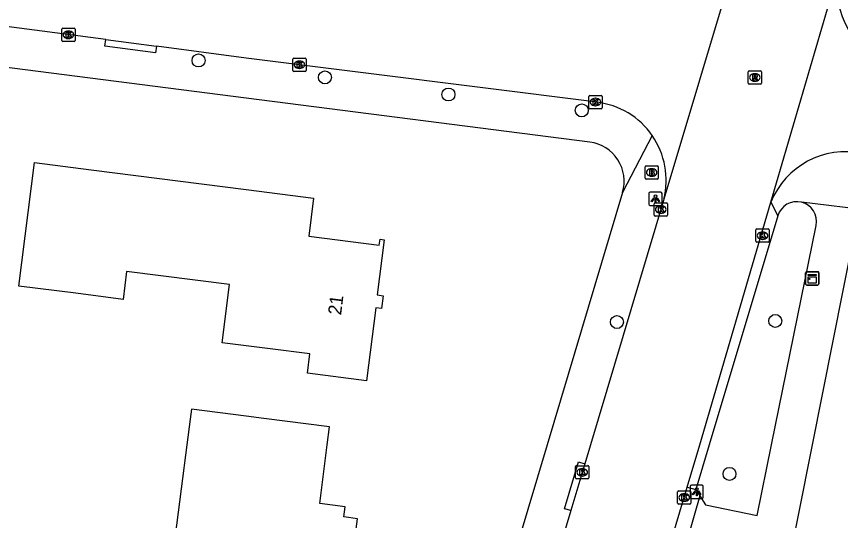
# Model space of a CAD drawing. Extents: x 162186 to 163152, y 385513 to 386513.
# Drawn here: x 162482.7 to 162544.8, y 385994.3 to 386032.3 of the extents above; entities that cross this region are included whole.
import ezdxf

# ---------------------------------------------------------------- set-up
doc = ezdxf.new("R2010")
doc.units = 0
for name, color, linetype in [('IMGEO_Boom', 7, 'Continuous'), ('IMGEO_Brandkraan', 7, 'Continuous'), ('IMGEO_Kast', 7, 'Continuous'), ('IMGEO_Kolk', 7, 'Continuous'), ('IMGEO_Lichtpunt', 7, 'Continuous'), ('IMGEO_Pand', 7, 'Continuous'), ('IMGEO_Pand_nummerreeks', 7, 'Continuous'), ('IMGEO_Rijbaan_lokaal_gesloten', 7, 'Continuous'), ('IMGEO_Rijbaan_lokaal_open', 7, 'Continuous'), ('IMGEO_Rioolput', 7, 'Continuous'), ('IMGEO_Voetpad_open', 7, 'Continuous')]:
    doc.layers.add(name, color=color, linetype=linetype)

msp = doc.modelspace()

# ---------------------------------------------------------------- linework, layer by layer
at = {"layer": 'IMGEO_Boom'}
for centre in [(162496.412, 386028.965), (162505.944, 386027.69), (162515.26, 386026.402), (162525.313, 386025.203), (162527.966, 386009.257), (162539.91, 386009.339), (162536.455, 385997.816)]:
    msp.add_circle(centre, 0.489, dxfattribs=at)
at = {"layer": 'IMGEO_Brandkraan'}
for p, q in [((162530.085, 386020.102), (162530.085, 386020.954)), ((162530.16, 386021.028), (162531.012, 386021.028)), ((162531.086, 386020.954), (162531.086, 386020.102)), ((162530.596, 386020.248), (162530.571, 386020.248)), ((162530.573, 386020.808), (162530.598, 386020.808)), ((162531.012, 386020.028), (162530.16, 386020.028))]:
    msp.add_line(p, q, dxfattribs=at)
for points in [[(162530.085, 386020.102), (162530.085, 386020.954)], [(162530.16, 386021.028), (162531.012, 386021.028)], [(162531.086, 386020.954), (162531.086, 386020.102)], [(162530.433, 386020.728), (162530.433, 386020.328), (162530.646, 386020.328)], [(162530.664, 386020.728), (162530.433, 386020.728)], [(162530.612, 386020.647), (162530.558, 386020.647), (162530.558, 386020.571)], [(162530.558, 386020.571), (162530.611, 386020.571)], [(162530.62, 386020.495), (162530.558, 386020.495), (162530.558, 386020.414)], [(162530.558, 386020.414), (162530.62, 386020.414)], [(162531.012, 386020.028), (162530.16, 386020.028)]]:
    msp.add_lwpolyline(points, dxfattribs=at)
for centre, radius, start, end in [((162530.162, 386020.952), 0.0765, 91.55205, 178.44795), ((162530.162, 386020.952), 0.0765, 91.55205, 178.44795), ((162531.01, 386020.952), 0.0765, 1.55205, 88.44795), ((162531.01, 386020.952), 0.0765, 1.55205, 88.44795), ((162530.613, 386020.609), 0.0379, 267.82845, 90.93552), ((162530.621, 386020.454), 0.0404, 269.87594, 90.50774), ((162530.652, 386020.579), 0.251, 268.66757, 293.53466), ((162530.668, 386020.583), 0.145, 59.4692, 91.53667), ((162530.693, 386020.63), 0.0922, 285.51372, 58.15012), ((162530.698, 386020.438), 0.105, 301.31148, 78.98903), ((162530.162, 386020.104), 0.0765, 181.55205, 268.44795), ((162530.162, 386020.104), 0.0765, 181.55205, 268.44795), ((162531.01, 386020.104), 0.0765, 271.55205, 358.44795), ((162531.01, 386020.104), 0.0765, 271.55205, 358.44795)]:
    msp.add_arc(centre, radius, start, end, dxfattribs=at)
for centre, major_axis, ratio, start_param, end_param in [((162530.572, 386020.528), (-0.387, 0.002), 0.722429, 4.712389, 7.853982), ((162530.597, 386020.528), (-0.39, 0.002), 0.717154, 1.570796, 4.712389)]:
    msp.add_ellipse(centre, major_axis=major_axis, ratio=ratio, start_param=start_param, end_param=end_param, dxfattribs=at)
at = {"layer": 'IMGEO_Kast'}
for p, q in [((162542.199, 386012.123), (162542.199, 386012.964)), ((162542.199, 386012.964), (162542.199, 386012.123)), ((162542.274, 386013.048), (162543.115, 386013.048)), ((162543.115, 386013.048), (162542.274, 386013.048)), ((162543.199, 386012.973), (162543.199, 386012.132)), ((162543.199, 386012.132), (162543.199, 386012.973)), ((162543.124, 386012.048), (162542.283, 386012.048)), ((162542.283, 386012.048), (162543.124, 386012.048))]:
    msp.add_line(p, q, dxfattribs=at)
for points in [[(162542.394, 386012.838), (162542.994, 386012.838), (162542.994, 386012.753), (162542.394, 386012.753), (162542.394, 386012.838)], [(162542.394, 386012.663), (162542.994, 386012.663), (162542.994, 386012.174), (162542.394, 386012.174), (162542.394, 386012.663)]]:
    msp.add_lwpolyline(points, dxfattribs=at)
msp.add_circle((162542.478, 386012.512), 0.0377, dxfattribs=at)
for centre, start, end in [((162542.277, 386012.97), 92.4484, 184.28452), ((162542.277, 386012.97), 92.4484, 184.28452), ((162543.121, 386012.97), 2.4484, 94.28452), ((162543.121, 386012.97), 2.4484, 94.28452), ((162542.277, 386012.126), 182.4484, 274.28452), ((162542.277, 386012.126), 182.4484, 274.28452), ((162543.121, 386012.126), 272.4484, 4.28452), ((162543.121, 386012.126), 272.4484, 4.28452)]:
    msp.add_arc(centre, 0.0779, start, end, dxfattribs=at)
at = {"layer": 'IMGEO_Kolk'}
for p, q in [((162486.175, 386031.402), (162487.027, 386031.402)), ((162486.1, 386030.476), (162486.1, 386031.328)), ((162486.588, 386031.182), (162486.613, 386031.182)), ((162487.101, 386031.328), (162487.101, 386030.476)), ((162487.027, 386030.402), (162486.175, 386030.402)), ((162486.611, 386030.622), (162486.586, 386030.622)), ((162503.52, 386028.218), (162503.52, 386029.07)), ((162503.595, 386029.144), (162504.447, 386029.144)), ((162504.008, 386028.924), (162504.033, 386028.924)), ((162504.521, 386029.07), (162504.521, 386028.218)), ((162504.031, 386028.364), (162504.006, 386028.364)), ((162504.447, 386028.144), (162503.595, 386028.144)), ((162525.842, 386025.408), (162525.842, 386026.26)), ((162525.917, 386026.334), (162526.769, 386026.334)), ((162526.33, 386026.114), (162526.355, 386026.114)), ((162526.843, 386026.26), (162526.843, 386025.408)), ((162526.769, 386025.334), (162525.917, 386025.334)), ((162526.353, 386025.554), (162526.328, 386025.554)), ((162530.773, 386017.314), (162530.773, 386018.166)), ((162530.848, 386018.24), (162531.7, 386018.24)), ((162531.261, 386018.02), (162531.286, 386018.02)), ((162531.774, 386018.166), (162531.774, 386017.314)), ((162531.7, 386017.24), (162530.848, 386017.24)), ((162531.284, 386017.46), (162531.259, 386017.46)), ((162538.447, 386015.342), (162538.447, 386016.194)), ((162538.522, 386016.268), (162539.374, 386016.268)), ((162538.935, 386016.048), (162538.96, 386016.048)), ((162539.448, 386016.194), (162539.448, 386015.342)), ((162539.374, 386015.268), (162538.522, 386015.268)), ((162538.958, 386015.488), (162538.933, 386015.488)), ((162524.848, 385997.51), (162524.848, 385998.362)), ((162524.923, 385998.436), (162525.775, 385998.436)), ((162525.336, 385998.216), (162525.361, 385998.216)), ((162525.849, 385998.362), (162525.849, 385997.51)), ((162525.775, 385997.436), (162524.923, 385997.436)), ((162525.359, 385997.656), (162525.334, 385997.656)), ((162532.546, 385995.609), (162532.546, 385996.461)), ((162532.621, 385996.535), (162533.473, 385996.535)), ((162533.034, 385996.315), (162533.059, 385996.315)), ((162533.547, 385996.461), (162533.547, 385995.609)), ((162533.473, 385995.535), (162532.621, 385995.535)), ((162533.057, 385995.755), (162533.032, 385995.755))]:
    msp.add_line(p, q, dxfattribs=at)
for points in [[(162486.175, 386031.402), (162487.027, 386031.402)], [(162486.1, 386030.476), (162486.1, 386031.328)], [(162486.421, 386031.102), (162486.544, 386031.102), (162486.544, 386030.951), (162486.674, 386031.102), (162486.838, 386031.102), (162486.692, 386030.951), (162486.845, 386030.702), (162486.693, 386030.702), (162486.608, 386030.866), (162486.544, 386030.799), (162486.544, 386030.702), (162486.421, 386030.702), (162486.421, 386031.102)], [(162487.101, 386031.328), (162487.101, 386030.476)], [(162487.027, 386030.402), (162486.175, 386030.402)], [(162503.52, 386028.218), (162503.52, 386029.07)], [(162503.595, 386029.144), (162504.447, 386029.144)], [(162504.521, 386029.07), (162504.521, 386028.218)], [(162503.841, 386028.844), (162503.964, 386028.844), (162503.964, 386028.693), (162504.094, 386028.844), (162504.258, 386028.844), (162504.112, 386028.693), (162504.265, 386028.444), (162504.113, 386028.444), (162504.028, 386028.608), (162503.964, 386028.541), (162503.964, 386028.444), (162503.841, 386028.444), (162503.841, 386028.844)], [(162504.447, 386028.144), (162503.595, 386028.144)], [(162525.842, 386025.408), (162525.842, 386026.26)], [(162525.917, 386026.334), (162526.769, 386026.334)], [(162526.163, 386026.034), (162526.286, 386026.034), (162526.286, 386025.883), (162526.416, 386026.034), (162526.58, 386026.034), (162526.434, 386025.883), (162526.587, 386025.634), (162526.435, 386025.634), (162526.35, 386025.798), (162526.286, 386025.731), (162526.286, 386025.634), (162526.163, 386025.634), (162526.163, 386026.034)], [(162526.843, 386026.26), (162526.843, 386025.408)], [(162526.769, 386025.334), (162525.917, 386025.334)], [(162530.773, 386017.314), (162530.773, 386018.166)], [(162530.848, 386018.24), (162531.7, 386018.24)], [(162531.094, 386017.94), (162531.217, 386017.94), (162531.217, 386017.789), (162531.347, 386017.94), (162531.511, 386017.94), (162531.365, 386017.789), (162531.518, 386017.54), (162531.366, 386017.54), (162531.281, 386017.704), (162531.217, 386017.637), (162531.217, 386017.54), (162531.094, 386017.54), (162531.094, 386017.94)], [(162531.774, 386018.166), (162531.774, 386017.314)], [(162531.7, 386017.24), (162530.848, 386017.24)], [(162538.447, 386015.342), (162538.447, 386016.194)], [(162538.522, 386016.268), (162539.374, 386016.268)], [(162538.768, 386015.968), (162538.891, 386015.968), (162538.891, 386015.817), (162539.021, 386015.968), (162539.185, 386015.968), (162539.039, 386015.817), (162539.192, 386015.568), (162539.04, 386015.568), (162538.955, 386015.732), (162538.891, 386015.665), (162538.891, 386015.568), (162538.768, 386015.568), (162538.768, 386015.968)], [(162539.448, 386016.194), (162539.448, 386015.342)], [(162539.374, 386015.268), (162538.522, 386015.268)], [(162524.848, 385997.51), (162524.848, 385998.362)], [(162524.923, 385998.436), (162525.775, 385998.436)], [(162525.169, 385998.136), (162525.292, 385998.136), (162525.292, 385997.985), (162525.422, 385998.136), (162525.586, 385998.136), (162525.44, 385997.985), (162525.593, 385997.736), (162525.441, 385997.736), (162525.356, 385997.9), (162525.292, 385997.833), (162525.292, 385997.736), (162525.169, 385997.736), (162525.169, 385998.136)], [(162525.849, 385998.362), (162525.849, 385997.51)], [(162525.775, 385997.436), (162524.923, 385997.436)], [(162532.546, 385995.609), (162532.546, 385996.461)], [(162532.621, 385996.535), (162533.473, 385996.535)], [(162532.867, 385996.235), (162532.99, 385996.235), (162532.99, 385996.084), (162533.12, 385996.235), (162533.284, 385996.235), (162533.138, 385996.084), (162533.291, 385995.835), (162533.139, 385995.835), (162533.054, 385995.999), (162532.99, 385995.932), (162532.99, 385995.835), (162532.867, 385995.835), (162532.867, 385996.235)], [(162533.547, 385996.461), (162533.547, 385995.609)], [(162533.473, 385995.535), (162532.621, 385995.535)]]:
    msp.add_lwpolyline(points, dxfattribs=at)
for centre, start, end in [((162486.177, 386031.326), 91.55205, 178.44795), ((162486.177, 386031.326), 91.55205, 178.44795), ((162487.025, 386031.326), 1.55205, 88.44795), ((162487.025, 386031.326), 1.55205, 88.44795), ((162486.177, 386030.478), 181.55205, 268.44795), ((162486.177, 386030.478), 181.55205, 268.44795), ((162487.025, 386030.478), 271.55205, 358.44795), ((162487.025, 386030.478), 271.55205, 358.44795), ((162503.597, 386029.068), 91.55205, 178.44795), ((162503.597, 386029.068), 91.55205, 178.44795), ((162504.445, 386029.068), 1.55205, 88.44795), ((162504.445, 386029.068), 1.55205, 88.44795), ((162503.597, 386028.22), 181.55205, 268.44795), ((162503.597, 386028.22), 181.55205, 268.44795), ((162504.445, 386028.22), 271.55205, 358.44795), ((162504.445, 386028.22), 271.55205, 358.44795), ((162525.919, 386026.258), 91.55205, 178.44795), ((162525.919, 386026.258), 91.55205, 178.44795), ((162526.767, 386026.258), 1.55205, 88.44795), ((162526.767, 386026.258), 1.55205, 88.44795), ((162525.919, 386025.41), 181.55205, 268.44795), ((162525.919, 386025.41), 181.55205, 268.44795), ((162526.767, 386025.41), 271.55205, 358.44795), ((162526.767, 386025.41), 271.55205, 358.44795), ((162530.85, 386018.164), 91.55205, 178.44795), ((162530.85, 386018.164), 91.55205, 178.44795), ((162531.698, 386018.164), 1.55205, 88.44795), ((162531.698, 386018.164), 1.55205, 88.44795), ((162530.85, 386017.316), 181.55205, 268.44795), ((162530.85, 386017.316), 181.55205, 268.44795), ((162531.698, 386017.316), 271.55205, 358.44795), ((162531.698, 386017.316), 271.55205, 358.44795), ((162538.524, 386016.192), 91.55205, 178.44795), ((162538.524, 386016.192), 91.55205, 178.44795), ((162539.372, 386016.192), 1.55205, 88.44795), ((162539.372, 386016.192), 1.55205, 88.44795), ((162538.524, 386015.344), 181.55205, 268.44795), ((162538.524, 386015.344), 181.55205, 268.44795), ((162539.372, 386015.344), 271.55205, 358.44795), ((162539.372, 386015.344), 271.55205, 358.44795), ((162524.925, 385998.36), 91.55205, 178.44795), ((162524.925, 385998.36), 91.55205, 178.44795), ((162525.773, 385998.36), 1.55205, 88.44795), ((162525.773, 385998.36), 1.55205, 88.44795), ((162524.925, 385997.512), 181.55205, 268.44795), ((162524.925, 385997.512), 181.55205, 268.44795), ((162525.773, 385997.512), 271.55205, 358.44795), ((162525.773, 385997.512), 271.55205, 358.44795), ((162532.623, 385996.459), 91.55205, 178.44795), ((162532.623, 385996.459), 91.55205, 178.44795), ((162533.471, 385996.459), 1.55205, 88.44795), ((162533.471, 385996.459), 1.55205, 88.44795), ((162532.623, 385995.611), 181.55205, 268.44795), ((162532.623, 385995.611), 181.55205, 268.44795), ((162533.471, 385995.611), 271.55205, 358.44795), ((162533.471, 385995.611), 271.55205, 358.44795)]:
    msp.add_arc(centre, 0.0765, start, end, dxfattribs=at)
for centre, major_axis, ratio, start_param, end_param in [((162486.587, 386030.902), (-0.387, 0.002), 0.722429, 4.712389, 7.853982), ((162486.612, 386030.902), (-0.39, 0.002), 0.717154, 1.570796, 4.712389), ((162504.007, 386028.644), (-0.387, 0.002), 0.722429, 4.712389, 7.853982), ((162504.032, 386028.644), (-0.39, 0.002), 0.717154, 1.570796, 4.712389), ((162526.329, 386025.834), (-0.387, 0.002), 0.722429, 4.712389, 7.853982), ((162526.354, 386025.834), (-0.39, 0.002), 0.717154, 1.570796, 4.712389), ((162531.26, 386017.74), (-0.387, 0.002), 0.722429, 4.712389, 7.853982), ((162531.285, 386017.74), (-0.39, 0.002), 0.717154, 1.570796, 4.712389), ((162538.934, 386015.768), (-0.387, 0.002), 0.722429, 4.712389, 7.853982), ((162538.959, 386015.768), (-0.39, 0.002), 0.717154, 1.570796, 4.712389), ((162525.335, 385997.936), (-0.387, 0.002), 0.722429, 4.712389, 7.853982), ((162525.36, 385997.936), (-0.39, 0.002), 0.717154, 1.570796, 4.712389), ((162533.033, 385996.035), (-0.387, 0.002), 0.722429, 4.712389, 7.853982), ((162533.058, 385996.035), (-0.39, 0.002), 0.717154, 1.570796, 4.712389)]:
    msp.add_ellipse(centre, major_axis=major_axis, ratio=ratio, start_param=start_param, end_param=end_param, dxfattribs=at)
at = {"layer": 'IMGEO_Lichtpunt'}
for p, q in [((162530.37, 386018.95), (162530.37, 386018.143)), ((162530.37, 386018.95), (162530.37, 386018.143)), ((162531.272, 386019.045), (162530.464, 386019.045)), ((162531.272, 386019.045), (162530.464, 386019.045)), ((162531.366, 386018.143), (162531.366, 386018.95)), ((162531.366, 386018.143), (162531.366, 386018.95)), ((162530.464, 386018.049), (162531.272, 386018.049)), ((162530.464, 386018.049), (162531.272, 386018.049)), ((162533.484, 385996.873), (162533.484, 385996.066)), ((162533.484, 385996.873), (162533.484, 385996.066)), ((162534.386, 385996.968), (162533.578, 385996.968)), ((162534.386, 385996.968), (162533.578, 385996.968)), ((162534.48, 385996.066), (162534.48, 385996.873)), ((162534.48, 385996.066), (162534.48, 385996.873)), ((162533.578, 385995.972), (162534.386, 385995.972)), ((162533.578, 385995.972), (162534.386, 385995.972))]:
    msp.add_line(p, q, dxfattribs=at)
for points in [[(162530.744, 386018.614), (162530.783, 386018.586), (162530.595, 386018.324), (162530.557, 386018.351), (162530.744, 386018.614)], [(162530.846, 386018.566), (162530.893, 386018.566), (162530.893, 386018.244), (162530.846, 386018.244), (162530.846, 386018.566)], [(162530.956, 386018.586), (162530.994, 386018.613), (162531.181, 386018.351), (162531.142, 386018.323), (162530.956, 386018.586)], [(162533.858, 385996.537), (162533.897, 385996.509), (162533.709, 385996.247), (162533.671, 385996.274), (162533.858, 385996.537)], [(162533.96, 385996.489), (162534.007, 385996.489), (162534.007, 385996.167), (162533.96, 385996.167), (162533.96, 385996.489)], [(162534.07, 385996.509), (162534.108, 385996.536), (162534.295, 385996.274), (162534.256, 385996.246), (162534.07, 385996.509)]]:
    msp.add_lwpolyline(points, dxfattribs=at)
for centre in [(162530.869, 386018.748), (162533.983, 385996.671)]:
    msp.add_circle(centre, 0.0994, dxfattribs=at)
for centre, start, end in [((162530.464, 386018.95), 90, 180), ((162530.464, 386018.95), 90, 180), ((162531.272, 386018.95), 0, 90), ((162531.272, 386018.95), 0, 90), ((162530.464, 386018.143), 180, 270), ((162530.464, 386018.143), 180, 270), ((162531.272, 386018.143), 270, 0), ((162531.272, 386018.143), 270, 360), ((162533.578, 385996.873), 90, 180), ((162533.578, 385996.873), 90, 180), ((162534.386, 385996.873), 0, 90), ((162534.386, 385996.873), 0, 90), ((162533.578, 385996.066), 180, 270), ((162533.578, 385996.066), 180, 270), ((162534.386, 385996.066), 270, 0), ((162534.386, 385996.066), 270, 360)]:
    msp.add_arc(centre, 0.0946, start, end, dxfattribs=at)
at = {"layer": 'IMGEO_Pand'}
for points in [[(162487.146, 386011.422), (162482.869, 386011.966), (162484.05, 386021.266), (162488.327, 386020.722), (162500, 386019.239), (162505.081, 386018.594), (162504.718, 386015.737), (162510.043, 386015.061), (162510.098, 386015.499), (162510.407, 386015.46), (162509.879, 386011.295), (162510.329, 386011.238), (162510.206, 386010.267), (162509.786, 386010.32), (162509.088, 386004.827), (162504.625, 386005.394), (162504.81, 386006.851), (162501.605, 386007.258), (162500, 386007.462), (162498.195, 386007.691), (162498.753, 386012.082), (162490.99, 386013.068), (162490.723, 386010.967), (162487.146, 386011.422)], [(162507.952, 385991.052), (162508.39, 385994.44), (162507.368, 385994.572), (162507.466, 385995.326), (162505.548, 385995.574), (162506.12, 386000), (162506.295, 386001.359), (162501.337, 386002), (162500, 386002.173), (162495.875, 386002.705), (162495.776, 386001.941), (162495.526, 386000), (162495.098, 385996.685), (162494.519, 385992.203)]]:
    msp.add_lwpolyline(points, dxfattribs=at)
at = {"layer": 'IMGEO_Rijbaan_lokaal_gesloten'}
for points in [[(162536.876, 386036.467), (162531.5, 386018.514)], [(162539.573, 386018.286), (162544.709, 386035.795)], [(162531.5, 386018.514), (162531.472, 386018.406), (162525.969, 386000), (162525.545, 385998.581)], [(162533.268, 385996.826), (162534.218, 386000), (162539.573, 386018.286)], [(162525.545, 385998.581), (162524.49, 385995.049)], [(162532.151, 385993.098), (162533.268, 385996.826)], [(162524.49, 385995.049), (162520.208, 385980.718)]]:
    msp.add_lwpolyline(points, dxfattribs=at)
at = {"layer": 'IMGEO_Rijbaan_lokaal_open'}
for points in [[(162489.419, 386030.537), (162472.666, 386032.732), (162470.821, 386032.968)], [(162489.419, 386030.537), (162493.24, 386030.037)], [(162526.463, 386025.819), (162500, 386029.151), (162493.24, 386030.037)]]:
    msp.add_lwpolyline(points, dxfattribs=at)
for centre, radius, start, end in [((162550.734, 386034.442), 6.175, 167.34096, 255.30154), ((162525.756, 386019.94), 5.921, 34.60648, 83.14706), ((162525.756, 386019.944), 5.92, 346.02078, 34.57206), ((162545.211, 386016.017), 6.077, 78.14133, 158.08048)]:
    msp.add_arc(centre, radius, start, end, dxfattribs=at)
at = {"layer": 'IMGEO_Rioolput'}
for p, q in [((162537.864, 386027.26), (162537.864, 386028.112)), ((162537.939, 386028.186), (162538.791, 386028.186)), ((162538.352, 386027.966), (162538.377, 386027.966)), ((162538.865, 386028.112), (162538.865, 386027.26)), ((162538.791, 386027.186), (162537.939, 386027.186)), ((162538.375, 386027.406), (162538.35, 386027.406))]:
    msp.add_line(p, q, dxfattribs=at)
for points in [[(162537.864, 386027.26), (162537.864, 386028.112)], [(162537.939, 386028.186), (162538.791, 386028.186)], [(162538.453, 386027.884), (162538.201, 386027.886), (162538.201, 386027.486)], [(162538.379, 386027.805), (162538.325, 386027.805), (162538.325, 386027.724)], [(162538.325, 386027.724), (162538.377, 386027.724)], [(162538.865, 386028.112), (162538.865, 386027.26)], [(162538.791, 386027.186), (162537.939, 386027.186)], [(162538.201, 386027.486), (162538.325, 386027.486), (162538.325, 386027.648), (162538.336, 386027.648)], [(162538.383, 386027.619), (162538.454, 386027.486), (162538.594, 386027.486), (162538.529, 386027.612)]]:
    msp.add_lwpolyline(points, dxfattribs=at)
for centre, radius, start, end in [((162537.941, 386028.11), 0.0765, 91.55205, 178.44795), ((162537.941, 386028.11), 0.0765, 91.55205, 178.44795), ((162538.361, 386027.913), 0.19, 274.7715, 282.96867), ((162538.385, 386027.709), 0.0964, 77.00612, 93.18647), ((162538.399, 386027.766), 0.0378, 276.66336, 79.67722), ((162538.452, 386027.774), 0.109, 350.36119, 89.41601), ((162538.45, 386027.774), 0.112, 277.58423, 350.98172), ((162538.434, 386027.559), 0.108, 29.51342, 73.79051), ((162538.789, 386028.11), 0.0765, 1.55205, 88.44795), ((162538.789, 386028.11), 0.0765, 1.55205, 88.44795), ((162537.941, 386027.262), 0.0765, 181.55205, 268.44795), ((162537.941, 386027.262), 0.0765, 181.55205, 268.44795), ((162538.335, 386027.595), 0.0533, 26.02933, 88.69889), ((162538.789, 386027.262), 0.0765, 271.55205, 358.44795), ((162538.789, 386027.262), 0.0765, 271.55205, 358.44795)]:
    msp.add_arc(centre, radius, start, end, dxfattribs=at)
for centre, major_axis, ratio, start_param, end_param in [((162538.351, 386027.686), (-0.387, 0.002), 0.722429, 4.712389, 7.853982), ((162538.376, 386027.686), (-0.39, 0.002), 0.717154, 1.570796, 4.712389)]:
    msp.add_ellipse(centre, major_axis=major_axis, ratio=ratio, start_param=start_param, end_param=end_param, dxfattribs=at)
at = {"layer": 'IMGEO_Voetpad_open'}
for points in [[(162525.924, 386022.81), (162500, 386026.135), (162427.629, 386035.417), (162425.539, 386035.686)], [(162493.24, 386030.037), (162493.175, 386029.536), (162489.354, 386030.037), (162489.419, 386030.537)], [(162530.63, 386023.303), (162528.389, 386019.021)], [(162528.389, 386019.021), (162522.698, 386000), (162510.965, 385960.784)], [(162539.573, 386018.286), (162540.098, 386017.265)], [(162547.236, 386017.634), (162541.889, 386018.283)], [(162540.098, 386017.265), (162534.925, 386000), (162533.926, 385996.644)], [(162534.23, 385996.154), (162534.648, 385995.479), (162538.534, 385994.688), (162539.616, 386000), (162542.986, 386016.54)], [(162533.9, 385956.179), (162537.876, 385976.531), (162538.512, 385978.937), (162542.711, 386000), (162545.809, 386015.54)], [(162524.49, 385995.049), (162524.01, 385995.192), (162525.066, 385998.724), (162525.545, 385998.581)], [(162533.268, 385996.826), (162533.926, 385996.644)], [(162533.926, 385996.644), (162534.23, 385996.154)], [(162534.23, 385996.154), (162533.303, 385993.021)]]:
    msp.add_lwpolyline(points, dxfattribs=at)
for centre, radius, start, end in [((162525.548, 386019.869), 2.965, 343.38467, 82.70876), ((162541.526, 386016.837), 1.491, 75.90166, 163.32593), ((162541.525, 386016.837), 1.491, 348.50429, 75.86625)]:
    msp.add_arc(centre, radius, start, end, dxfattribs=at)

# ---------------------------------------------------------------- texts
at = {"layer": 'IMGEO_Pand_nummerreeks'}
msp.add_text('21', height=1, rotation=82.92871, dxfattribs=at).set_placement((162507.16, 386009.747))

doc.saveas('drawing.dxf')
